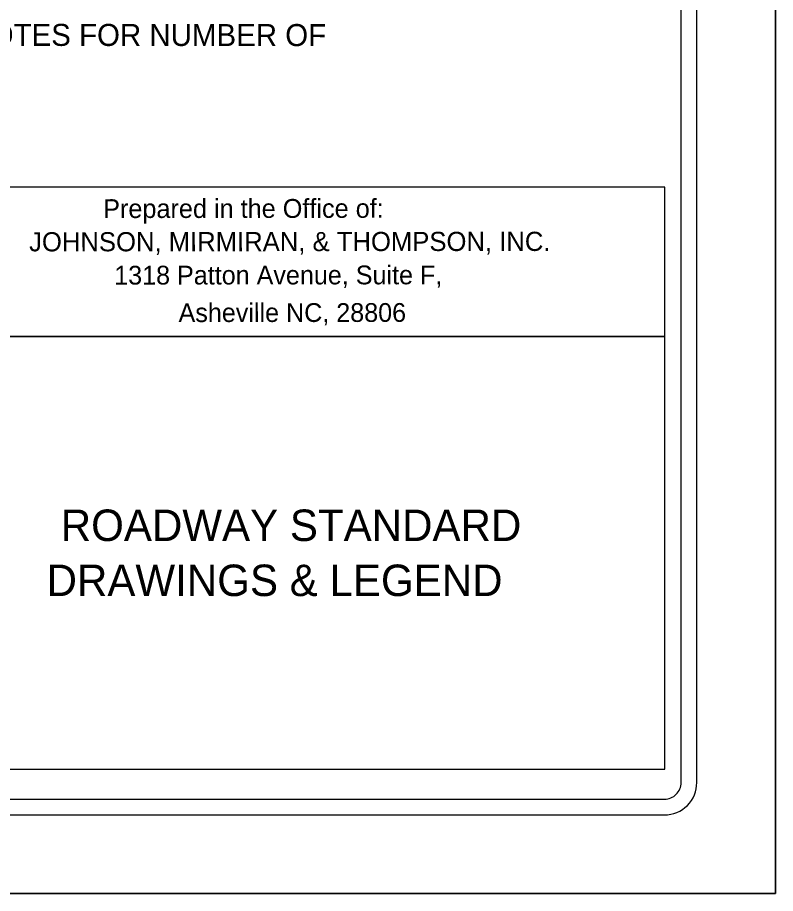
# Model space of a CAD drawing. Extents: x 1403867 to 1405555, y 486423 to 487523.
# Drawn here: x 1405314.5 to 1405555.4, y 486422.7 to 486701.2 of the extents above; entities that cross this region are included whole.
import ezdxf

# ---------------------------------------------------------------- set-up
doc = ezdxf.new("R2010")
doc.units = 0
for name, color, linetype in [('DEV BORDER CELL', 7, 'Continuous'), ('Sheet Plan CELL', 7, 'Continuous'), ('Sheet Plot Border Outside CELL', 7, 'Continuous'), ('Sheet Title CELL', 7, 'Continuous')]:
    doc.layers.add(name, color=color, linetype=linetype)

msp = doc.modelspace()

# ---------------------------------------------------------------- linework, layer by layer
at = {"layer": 'DEV BORDER CELL'}
for p, q in [((1405525.36, 486458), (1405525.36, 487487.44)), ((1405530.36, 486458), (1405530.36, 487487.44)), ((1404608.13, 486452.72), (1405520.08, 486452.72)), ((1404040.64, 486447.72), (1405520.08, 486447.72))]:
    msp.add_line(p, q, dxfattribs=at)
msp.add_lwpolyline([(1405520.21, 486599.77), (1405284.21, 486599.77), (1405284.21, 486462.27), (1405520.21, 486462.27)], close=True, dxfattribs=at)
for radius in [10.29, 5.29, 5.29]:
    msp.add_arc((1405520.08, 486458), radius, 270, 0.0001, dxfattribs=at)
at = {"layer": 'Sheet Plan CELL'}
msp.add_lwpolyline([(1405520.21, 486647.29), (1405228.54, 486647.29), (1405228.54, 486599.77), (1405520.21, 486599.77)], close=True, dxfattribs=at)
at = {"layer": 'Sheet Plot Border Outside CELL'}
for points in [[(1403867.36, 486422.72), (1403867.36, 487522.72), (1405555.36, 487522.72), (1405555.36, 486422.72)], [(1403867.36, 487522.72), (1405555.36, 487522.72), (1405555.36, 486422.72), (1403867.36, 486422.72)], [(1403867.36, 486422.72), (1405555.36, 486422.72), (1405555.36, 487522.72), (1403867.36, 487522.72)]]:
    msp.add_lwpolyline(points, close=True, dxfattribs=at)

# ---------------------------------------------------------------- texts
at = {"layer": 'DEV BORDER CELL'}
msp.add_text('REFER TO GENERAL NOTES FOR NUMBER OF', height=7, rotation=359.9598, dxfattribs=at).set_placement((1405201.94, 486692.25))
for s, p in [('ROADWAY STANDARD ', (1405328.24, 486534.77)), ('DRAWINGS & LEGEND', (1405323.74, 486517.27))]:
    msp.add_text(s, height=10, dxfattribs=at).set_placement(p)
at = {"layer": 'Sheet Title CELL'}
for s, height, p in [('Prepared in the Office of:', 5.9987, (1405341.71, 486637.44)), ('JOHNSON, MIRMIRAN, & THOMPSON, INC.', 6.0929, (1405318.19, 486626.84)), ('1318 Patton Avenue, Suite F,', 5.9679, (1405345.23, 486616.29)), ('Asheville NC, 28806', 5.9679, (1405365.68, 486604.37))]:
    msp.add_text(s, height=height, rotation=0.0516, dxfattribs=at).set_placement(p)

doc.saveas('drawing.dxf')
